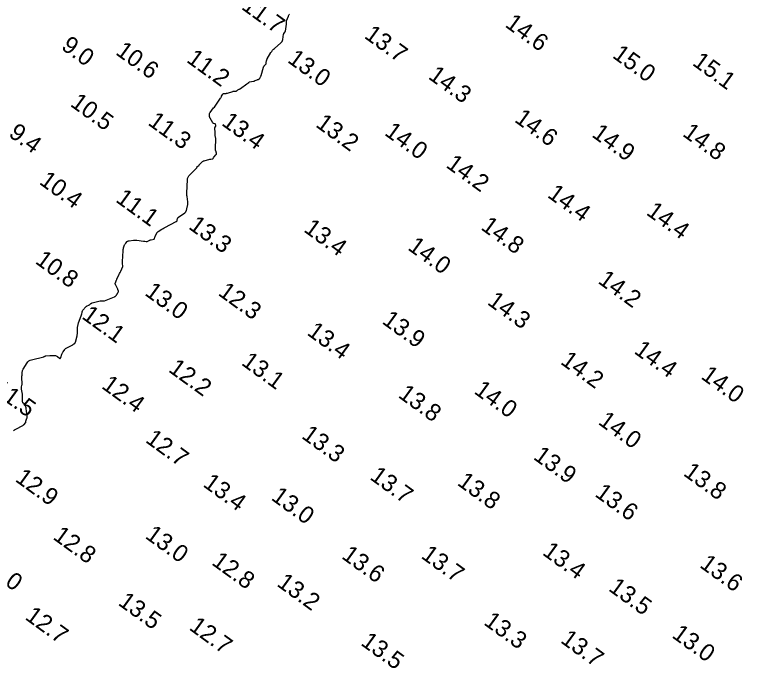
# Model space of a CAD drawing. Extents: x 815352 to 820877, y 582403 to 597439.
# Drawn here: x 818223.8 to 818436.7, y 586491.6 to 586682.6 of the extents above; entities that cross this region are included whole.
import ezdxf

# ---------------------------------------------------------------- set-up
doc = ezdxf.new("R2010")
doc.units = 0
doc.layers.add('V-CONT-EL12', color=7, linetype='Continuous')
doc.layers.add('V-TOPO-SOUN', color=7, linetype='Continuous')

msp = doc.modelspace()

# ---------------------------------------------------------------- linework, layer by layer
at = {"layer": 'V-CONT-EL12'}
msp.add_lwpolyline([(818223.41, 586561.04), (818223.77, 586561.22), (818224.13, 586561.41), (818226.2, 586562.56), (818226.3, 586562.62), (818226.39, 586562.68), (818226.48, 586562.76), (818226.56, 586562.84), (818226.97, 586563.29), (818226.99, 586563.33), (818227.01, 586563.37), (818227.02, 586563.41), (818227.02, 586563.45), (818227, 586563.62), (818227, 586563.67), (818227, 586563.71), (818227.01, 586563.75), (818227.02, 586563.79), (818227.37, 586564.7), (818227.4, 586564.8), (818227.42, 586564.9), (818227.43, 586565), (818227.42, 586565.11), (818227.4, 586565.53), (818227.39, 586565.63), (818227.38, 586565.73), (818227.37, 586565.84), (818227.35, 586565.94), (818227.16, 586567.48), (818227.14, 586567.59), (818227.13, 586567.71), (818227.1, 586567.82), (818227.08, 586567.93), (818226.97, 586568.36), (818226.93, 586568.47), (818226.88, 586568.56), (818226.82, 586568.65), (818226.74, 586568.72), (818226.28, 586569.09), (818226.19, 586569.18), (818226.12, 586569.29), (818226.09, 586569.4), (818226.07, 586569.53), (818226.09, 586570.74), (818226.09, 586570.98), (818226.08, 586571.23), (818226.06, 586571.47), (818226.03, 586571.72), (818225.82, 586573.14), (818225.8, 586573.29), (818225.79, 586573.44), (818225.8, 586573.59), (818225.82, 586573.74), (818225.92, 586574.35), (818225.95, 586574.5), (818225.96, 586574.65), (818225.97, 586574.8), (818225.97, 586574.96), (818225.92, 586576.28), (818225.91, 586576.52), (818225.91, 586576.75), (818225.92, 586576.99), (818225.94, 586577.22), (818226.01, 586578.16), (818226.04, 586578.39), (818226.1, 586578.61), (818226.18, 586578.83), (818226.29, 586579.03), (818227.4, 586580.8), (818227.65, 586581.13), (818227.94, 586581.39), (818228.29, 586581.59), (818228.68, 586581.73), (818232.29, 586582.63), (818232.34, 586582.64), (818232.39, 586582.66), (818232.44, 586582.69), (818232.48, 586582.71), (818232.66, 586582.83), (818232.71, 586582.85), (818232.76, 586582.87), (818232.81, 586582.88), (818232.86, 586582.89), (818234.05, 586582.94), (818234.24, 586582.95), (818234.43, 586582.96), (818234.62, 586582.96), (818234.81, 586582.96), (818235.57, 586582.97), (818235.76, 586582.95), (818235.93, 586582.91), (818236.1, 586582.83), (818236.25, 586582.73), (818236.84, 586582.23), (818236.98, 586582.15), (818237.09, 586582.14), (818237.18, 586582.21), (818237.25, 586582.35), (818237.58, 586583.38), (818237.65, 586583.57), (818237.73, 586583.75), (818237.83, 586583.92), (818237.94, 586584.09), (818238.41, 586584.74), (818238.53, 586584.9), (818238.68, 586585.03), (818238.83, 586585.15), (818239.01, 586585.25), (818240.54, 586586), (818240.6, 586586.03), (818240.65, 586586.06), (818240.71, 586586.1), (818240.76, 586586.14), (818241.01, 586586.33), (818241.04, 586586.36), (818241.08, 586586.39), (818241.12, 586586.41), (818241.16, 586586.44), (818241.33, 586586.53), (818241.36, 586586.56), (818241.4, 586586.59), (818241.42, 586586.63), (818241.44, 586586.67), (818241.62, 586587.19), (818241.66, 586587.29), (818241.69, 586587.4), (818241.72, 586587.5), (818241.75, 586587.61), (818242.02, 586588.7), (818242.06, 586588.91), (818242.09, 586589.12), (818242.11, 586589.33), (818242.12, 586589.55), (818242.12, 586590.51), (818242.13, 586590.68), (818242.14, 586590.84), (818242.16, 586591), (818242.18, 586591.16), (818242.34, 586592.04), (818242.35, 586592.08), (818242.36, 586592.13), (818242.36, 586592.17), (818242.37, 586592.22), (818242.4, 586592.4), (818242.41, 586592.44), (818242.42, 586592.49), (818242.43, 586592.53), (818242.45, 586592.57), (818243.19, 586594.53), (818243.24, 586594.67), (818243.29, 586594.81), (818243.33, 586594.95), (818243.36, 586595.09), (818243.49, 586595.67), (818243.53, 586595.81), (818243.58, 586595.94), (818243.65, 586596.07), (818243.74, 586596.18), (818244.61, 586597.19), (818244.69, 586597.27), (818244.78, 586597.35), (818244.87, 586597.41), (818244.97, 586597.46), (818245.41, 586597.65), (818245.5, 586597.69), (818245.59, 586597.74), (818245.68, 586597.8), (818245.76, 586597.87), (818246.08, 586598.14), (818246.16, 586598.2), (818246.25, 586598.26), (818246.35, 586598.3), (818246.45, 586598.33), (818248.76, 586598.96), (818248.85, 586598.98), (818248.94, 586598.99), (818249.04, 586598.99), (818249.13, 586598.98), (818249.62, 586598.9), (818249.65, 586598.89), (818249.69, 586598.89), (818249.73, 586598.9), (818249.77, 586598.9), (818249.91, 586598.94), (818249.95, 586598.95), (818249.99, 586598.96), (818250.02, 586598.97), (818250.06, 586598.98), (818253, 586600.15), (818253.07, 586600.18), (818253.14, 586600.22), (818253.19, 586600.27), (818253.25, 586600.32), (818253.46, 586600.54), (818253.51, 586600.6), (818253.56, 586600.66), (818253.6, 586600.72), (818253.64, 586600.78), (818254.04, 586601.46), (818254.08, 586601.53), (818254.09, 586601.6), (818254.09, 586601.68), (818254.08, 586601.76), (818253.99, 586602.07), (818253.97, 586602.14), (818253.94, 586602.22), (818253.91, 586602.29), (818253.88, 586602.37), (818253.22, 586603.73), (818253.17, 586603.85), (818253.16, 586603.98), (818253.17, 586604.11), (818253.21, 586604.24), (818253.42, 586604.75), (818253.48, 586604.88), (818253.53, 586605.01), (818253.59, 586605.14), (818253.65, 586605.26), (818254.35, 586606.7), (818254.46, 586606.94), (818254.58, 586607.18), (818254.69, 586607.42), (818254.8, 586607.66), (818255.38, 586608.96), (818255.41, 586609.04), (818255.42, 586609.12), (818255.43, 586609.2), (818255.41, 586609.29), (818255.33, 586609.66), (818255.31, 586609.73), (818255.3, 586609.79), (818255.29, 586609.86), (818255.28, 586609.93), (818255.26, 586610.2), (818255.25, 586610.26), (818255.25, 586610.33), (818255.25, 586610.4), (818255.25, 586610.46), (818255.44, 586613.56), (818255.46, 586613.77), (818255.5, 586613.98), (818255.54, 586614.19), (818255.61, 586614.39), (818255.91, 586615.3), (818255.97, 586615.45), (818256.05, 586615.58), (818256.14, 586615.71), (818256.24, 586615.82), (818256.7, 586616.26), (818256.82, 586616.36), (818256.95, 586616.44), (818257.09, 586616.49), (818257.24, 586616.52), (818258.46, 586616.67), (818258.72, 586616.7), (818258.97, 586616.71), (818259.23, 586616.7), (818259.49, 586616.67), (818261.46, 586616.41), (818261.55, 586616.4), (818261.64, 586616.39), (818261.72, 586616.37), (818261.81, 586616.35), (818262.16, 586616.27), (818262.24, 586616.26), (818262.33, 586616.26), (818262.41, 586616.28), (818262.49, 586616.31), (818263.13, 586616.61), (818263.26, 586616.67), (818263.4, 586616.72), (818263.54, 586616.77), (818263.68, 586616.81), (818264.5, 586617.01), (818264.57, 586617.04), (818264.62, 586617.08), (818264.66, 586617.13), (818264.68, 586617.2), (818264.75, 586617.51), (818264.76, 586617.59), (818264.79, 586617.66), (818264.81, 586617.74), (818264.85, 586617.81), (818265.28, 586618.68), (818265.37, 586618.84), (818265.48, 586618.98), (818265.61, 586619.11), (818265.76, 586619.22), (818266.75, 586619.84), (818266.97, 586619.97), (818267.19, 586620.1), (818267.42, 586620.23), (818267.65, 586620.35), (818270.97, 586622.1), (818271.08, 586622.17), (818271.16, 586622.25), (818271.23, 586622.36), (818271.27, 586622.48), (818271.4, 586622.99), (818271.44, 586623.11), (818271.5, 586623.22), (818271.58, 586623.32), (818271.68, 586623.4), (818273.54, 586624.69), (818273.61, 586624.75), (818273.67, 586624.82), (818273.73, 586624.89), (818273.78, 586624.97), (818273.99, 586625.43), (818274, 586625.46), (818274.02, 586625.5), (818274.03, 586625.53), (818274.03, 586625.57), (818274.06, 586625.72), (818274.06, 586625.76), (818274.07, 586625.79), (818274.08, 586625.83), (818274.09, 586625.87), (818274.39, 586627.06), (818274.41, 586627.13), (818274.42, 586627.2), (818274.42, 586627.27), (818274.41, 586627.34), (818274.39, 586627.62), (818274.38, 586627.69), (818274.37, 586627.76), (818274.36, 586627.83), (818274.36, 586627.9), (818274.15, 586629.42), (818274.12, 586629.7), (818274.1, 586629.98), (818274.1, 586630.26), (818274.1, 586630.54), (818274.27, 586634.25), (818274.33, 586634.69), (818274.46, 586635.09), (818274.67, 586635.46), (818274.96, 586635.79), (818276.81, 586637.57), (818276.86, 586637.63), (818276.9, 586637.69), (818276.94, 586637.75), (818276.97, 586637.82), (818277.08, 586638.1), (818277.11, 586638.16), (818277.16, 586638.22), (818277.2, 586638.27), (818277.26, 586638.32), (818277.57, 586638.52), (818277.65, 586638.57), (818277.71, 586638.63), (818277.78, 586638.68), (818277.84, 586638.75), (818278.52, 586639.5), (818278.66, 586639.63), (818278.82, 586639.74), (818278.99, 586639.83), (818279.17, 586639.89), (818280.78, 586640.3), (818280.87, 586640.32), (818280.96, 586640.34), (818281.06, 586640.36), (818281.15, 586640.37), (818281.58, 586640.41), (818281.65, 586640.42), (818281.7, 586640.45), (818281.75, 586640.5), (818281.79, 586640.55), (818281.91, 586640.81), (818281.94, 586640.87), (818281.98, 586640.93), (818282.02, 586640.99), (818282.07, 586641.04), (818282.6, 586641.6), (818282.68, 586641.71), (818282.73, 586641.83), (818282.75, 586641.97), (818282.72, 586642.11), (818282.53, 586642.78), (818282.5, 586642.9), (818282.48, 586643.03), (818282.47, 586643.15), (818282.46, 586643.27), (818282.45, 586643.77), (818282.45, 586643.89), (818282.46, 586644.02), (818282.46, 586644.14), (818282.47, 586644.26), (818282.58, 586645.53), (818282.59, 586645.75), (818282.59, 586645.96), (818282.58, 586646.18), (818282.55, 586646.4), (818282.41, 586647.26), (818282.38, 586647.48), (818282.36, 586647.7), (818282.34, 586647.92), (818282.33, 586648.14), (818282.28, 586649.43), (818282.29, 586649.5), (818282.3, 586649.58), (818282.33, 586649.65), (818282.37, 586649.71), (818282.56, 586649.98), (818282.59, 586650.04), (818282.61, 586650.1), (818282.61, 586650.16), (818282.59, 586650.22), (818282.5, 586650.48), (818282.47, 586650.53), (818282.43, 586650.58), (818282.38, 586650.61), (818282.32, 586650.64), (818281.96, 586650.73), (818281.88, 586650.76), (818281.81, 586650.8), (818281.75, 586650.86), (818281.71, 586650.92), (818280.89, 586652.3), (818280.82, 586652.42), (818280.77, 586652.56), (818280.74, 586652.7), (818280.72, 586652.84), (818280.7, 586653.43), (818280.71, 586653.58), (818280.74, 586653.71), (818280.79, 586653.84), (818280.87, 586653.96), (818281.93, 586655.31), (818282.14, 586655.57), (818282.34, 586655.84), (818282.53, 586656.11), (818282.72, 586656.38), (818283.92, 586658.15), (818284.01, 586658.28), (818284.09, 586658.42), (818284.18, 586658.56), (818284.26, 586658.7), (818284.61, 586659.33), (818284.68, 586659.42), (818284.77, 586659.49), (818284.87, 586659.53), (818284.98, 586659.55), (818285.48, 586659.56), (818285.6, 586659.56), (818285.72, 586659.58), (818285.84, 586659.6), (818285.96, 586659.63), (818287.52, 586660.12), (818287.61, 586660.15), (818287.71, 586660.17), (818287.81, 586660.18), (818287.91, 586660.18), (818288.38, 586660.19), (818288.44, 586660.19), (818288.5, 586660.21), (818288.56, 586660.24), (818288.61, 586660.27), (818288.81, 586660.44), (818288.86, 586660.47), (818288.92, 586660.51), (818288.97, 586660.54), (818289.03, 586660.57), (818289.43, 586660.77), (818289.51, 586660.81), (818289.59, 586660.86), (818289.67, 586660.91), (818289.75, 586660.96), (818291.67, 586662.31), (818291.73, 586662.36), (818291.8, 586662.41), (818291.86, 586662.47), (818291.92, 586662.53), (818292.16, 586662.76), (818292.22, 586662.82), (818292.29, 586662.86), (818292.37, 586662.89), (818292.44, 586662.91), (818293.61, 586663.12), (818293.73, 586663.14), (818293.86, 586663.18), (818293.98, 586663.22), (818294.1, 586663.27), (818294.67, 586663.53), (818294.74, 586663.56), (818294.82, 586663.59), (818294.89, 586663.62), (818294.96, 586663.65), (818295.26, 586663.77), (818295.32, 586663.81), (818295.38, 586663.86), (818295.43, 586663.91), (818295.46, 586663.98), (818295.64, 586664.4), (818295.67, 586664.49), (818295.71, 586664.59), (818295.74, 586664.69), (818295.77, 586664.78), (818296.48, 586667.21), (818296.52, 586667.33), (818296.58, 586667.44), (818296.65, 586667.54), (818296.73, 586667.63), (818297.09, 586668), (818297.17, 586668.09), (818297.24, 586668.19), (818297.28, 586668.31), (818297.31, 586668.43), (818297.4, 586669.11), (818297.42, 586669.26), (818297.47, 586669.41), (818297.52, 586669.56), (818297.6, 586669.69), (818298.67, 586671.48), (818298.89, 586671.82), (818299.13, 586672.13), (818299.4, 586672.42), (818299.69, 586672.69), (818301.57, 586674.28), (818301.78, 586674.49), (818301.94, 586674.72), (818302.05, 586674.98), (818302.12, 586675.26), (818302.37, 586676.87), (818302.39, 586676.96), (818302.42, 586677.03), (818302.46, 586677.11), (818302.51, 586677.17), (818302.75, 586677.43), (818302.8, 586677.49), (818302.84, 586677.56), (818302.87, 586677.64), (818302.89, 586677.72), (818303.18, 586679.74), (818303.2, 586679.83), (818303.2, 586679.92), (818303.2, 586680), (818303.2, 586680.09), (818303.19, 586680.44), (818303.19, 586680.52), (818303.2, 586680.61), (818303.21, 586680.69), (818303.24, 586680.77), (818303.75, 586682.06), (818303.82, 586682.23), (818303.91, 586682.4), (818303.99, 586682.56), (818304.09, 586682.72)], dxfattribs=at)

# ---------------------------------------------------------------- texts
at = {"layer": 'V-TOPO-SOUN'}
for s, p in [('11.7 ', (818289.78, 586684.39)), ('14.6 ', (818366.82, 586679.2)), ('13.7 ', (818325.67, 586675.93)), ('9.0', (818237.13, 586672.67)), ('10.6 ', (818253.01, 586671.13)), ('11.2 ', (818273.73, 586668.91)), ('13.0 ', (818303.23, 586668.85)), ('15.0 ', (818398.18, 586670.2)), ('15.1 ', (818421.55, 586668.01)), ('14.3 ', (818344.37, 586664.05)), ('10.5 ', (818239.77, 586656.04)), ('14.6 ', (818369.57, 586651.45)), ('11.3 ', (818262.45, 586650.57)), ('13.4 ', (818283.97, 586650.47)), ('13.2 ', (818311.46, 586650.01)), ('9.4', (818221.75, 586647.2)), ('14.0 ', (818331.58, 586647.59)), ('14.9 ', (818392.17, 586647.09)), ('14.8 ', (818418.68, 586647.32)), ('14.2 ', (818349.55, 586638.16)), ('10.4 ', (818230.69, 586633.28)), ('11.1 ', (818253.02, 586628.08)), ('14.4 ', (818379.18, 586629.44)), ('14.4 ', (818408.08, 586624.32)), ('13.3 ', (818274.32, 586620.22)), ('14.8 ', (818359.76, 586619.99)), ('13.4 ', (818307.98, 586619.36)), ('14.0 ', (818338.37, 586614.09)), ('10.8 ', (818229.51, 586610.11)), ('14.2 ', (818393.97, 586604.31)), ('13.0 ', (818261.53, 586600.81)), ('12.3 ', (818282.98, 586600.8)), ('14.3 ', (818361.63, 586598.1)), ('12.1 ', (818243.14, 586593.99)), ('13.9 ', (818330.88, 586592.53)), ('13.4 ', (818308.94, 586589.21)), ('14.4 ', (818404.51, 586583.83)), ('13.1 ', (818289.76, 586580.44)), ('14.2 ', (818383.02, 586580.72)), ('12.2 ', (818268.45, 586578.45)), ('14.0 ', (818424.06, 586576.43)), ('12.4 ', (818248.9, 586573.63)), ('11.5 ', (818217.06, 586572.38)), ('13.8 ', (818335.58, 586570.97)), ('14.0 ', (818357.76, 586572.1)), ('14.0 ', (818394.04, 586563.11)), ('12.7 ', (818261.72, 586557.85)), ('13.3 ', (818307.36, 586559.03)), ('13.9 ', (818375.08, 586552.9)), ('13.7 ', (818327.31, 586547.02)), ('13.8 ', (818418.91, 586548.14)), ('12.9 ', (818223.67, 586546.43)), ('13.4 ', (818278.55, 586544.92)), ('13.8 ', (818352.83, 586545.35)), ('13.0 ', (818298.47, 586541.03)), ('13.6 ', (818393.06, 586542.06)), ('12.8 ', (818234.69, 586529.54)), ('13.0 ', (818261.66, 586529.81)), ('13.6 ', (818319.05, 586523.92)), ('13.7 ', (818342.27, 586524.02)), ('13.4 ', (818377.73, 586524.98)), ('13.0 ', (818213.2, 586521.57)), ('12.8 ', (818281.08, 586522.09)), ('13.6 ', (818423.67, 586521.33)), ('13.2 ', (818300.14, 586515.85)), ('13.5 ', (818397.05, 586514.48)), ('13.5 ', (818253.74, 586510.31)), ('12.7 ', (818226.55, 586506.11)), ('13.3 ', (818360.58, 586504.57)), ('12.7 ', (818274.49, 586503.09)), ('13.0 ', (818415.57, 586500.81)), ('13.5 ', (818324.64, 586498.6)), ('13.7 ', (818383.02, 586499.32))]:
    msp.add_text(s, height=5, rotation=324, dxfattribs=at).set_placement(p)

doc.saveas('drawing.dxf')
